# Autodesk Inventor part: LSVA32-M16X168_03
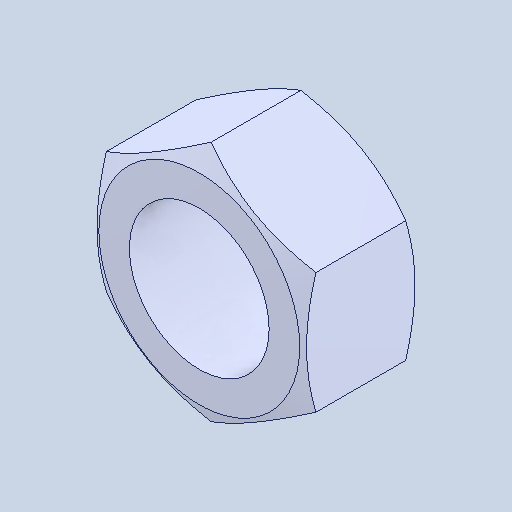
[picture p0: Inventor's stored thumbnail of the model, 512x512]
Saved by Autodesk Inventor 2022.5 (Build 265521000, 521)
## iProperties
Created: 2024-08
Part Number: LSVA32-M16X168_03
Material: 一般
Document SubType Name: Modeling
Designer: ImaoCorp
Density: 1 g/cm^3
Appearance: 既定
Author: ImaoCorp
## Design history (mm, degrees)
feature "LSVA32-M16X168_03"
node "ソリッド1"
